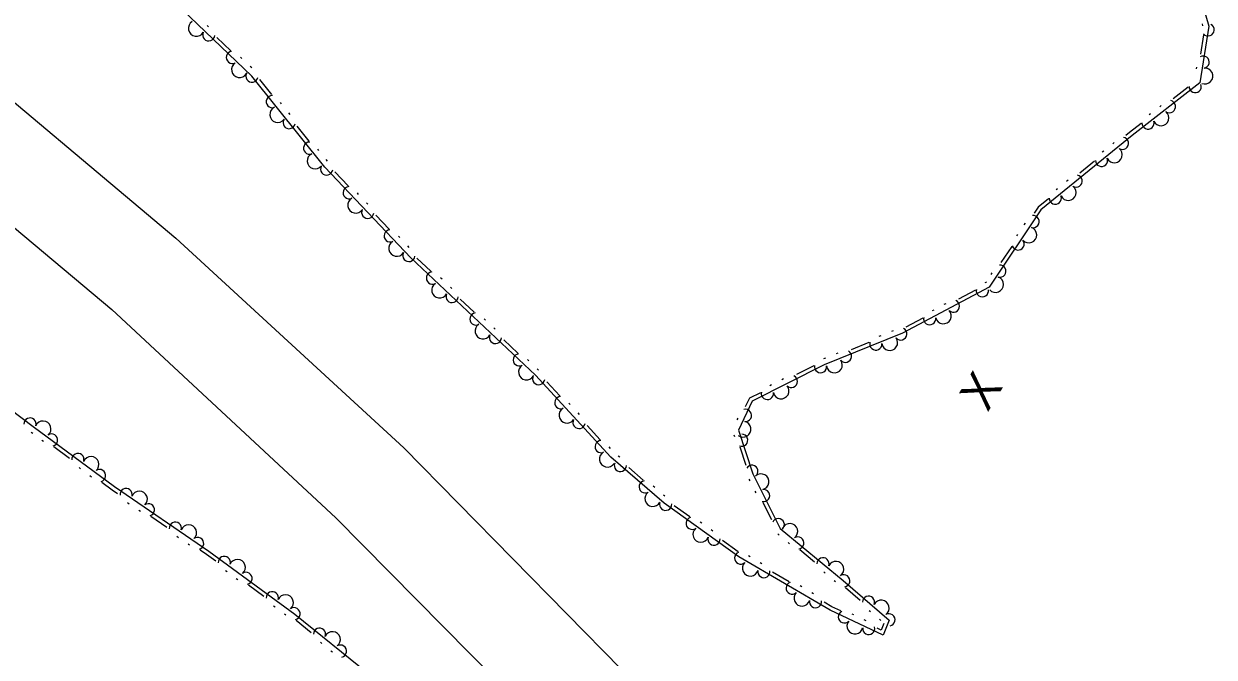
# Model space of a CAD drawing. Extents: x 2030130 to 2036320, y 723205 to 762423.
# Drawn here: x 2033698.8 to 2033952.5, y 760133.9 to 760268.9 of the extents above; entities that cross this region are included whole.
import ezdxf

# ---------------------------------------------------------------- set-up
doc = ezdxf.new("R2010")
doc.units = 0
doc.layers.add('Draft_Station Labels Major', color=7, linetype='Continuous')
doc.layers.add('Draft_Station Tics Major', color=7, linetype='Continuous')

msp = doc.modelspace()

# ---------------------------------------------------------------- linework, layer by layer
at = {"layer": 'Draft_Station Labels Major'}
for points in [[(2033680.58, 760265.74), (2033731.15, 760223.23), (2033779.8, 760178.5), (2033826.1, 760131.35), (2033869.94, 760081.9)], [(2033667.56, 760249.84), (2033717.53, 760207.99), (2033765.27, 760163.58), (2033811.07, 760117.18), (2033854.41, 760068.47)]]:
    msp.add_lwpolyline(points, dxfattribs=at)
at = {"layer": 'Draft_Station Tics Major'}
for points in [[(2033411.94, 760372.87), (2033436.62, 760363.72), (2033457.72, 760353.14), (2033472.09, 760345.15), (2033486.23, 760335.96), (2033505.08, 760321.88), (2033526.01, 760304.91), (2033549.26, 760286.66), (2033572.92, 760268.98), (2033588.53, 760260.15), (2033618.88, 760241.01), (2033641.56, 760226.3), (2033661.86, 760212.37), (2033683.46, 760196.15), (2033700.78, 760183.09), (2033718.09, 760170.27), (2033738.2, 760156.52), (2033756.52, 760143.06), (2033772.39, 760130.26)], [(2033949.39, 760275.12), (2033951.3, 760268.42), (2033949.43, 760256.31), (2033934.97, 760245.11), (2033915.56, 760229.27), (2033904.54, 760212.79), (2033886.03, 760202.95), (2033869.32, 760196.2), (2033854.03, 760188.48), (2033851.07, 760182.28), (2033854.12, 760172.95), (2033859.97, 760161.34), (2033873.42, 760150.27), (2033883.23, 760141.81), (2033881.91, 760138.58), (2033870.62, 760143.93), (2033851.14, 760155.28), (2033835.28, 760166.7), (2033823.91, 760176.51), (2033807.81, 760194.03), (2033781.27, 760219.06), (2033762.96, 760238.34), (2033747.39, 760257.77), (2033730.92, 760273.5)], [(2033738.15, 760268.29), (2033737.85, 760268.58)], [(2033949.89, 760268.88), (2033950, 760268.49)], [(2033742.91, 760263.18), (2033739.94, 760266.01)], [(2033950.18, 760266.53), (2033949.56, 760262.47)], [(2033745.27, 760261.49), (2033744.97, 760261.78)], [(2033747.34, 760259.51), (2033747.05, 760259.79)], [(2033948.71, 760259.7), (2033948.65, 760259.3)], [(2033751.61, 760253.81), (2033749.05, 760257.01)], [(2033946.96, 760255.43), (2033943.72, 760252.92)], [(2033753.73, 760251.82), (2033753.47, 760252.14)], [(2033941.19, 760251.48), (2033940.87, 760251.23)], [(2033755.52, 760249.58), (2033755.27, 760249.9)], [(2033938.92, 760249.73), (2033938.6, 760249.48)], [(2033759.56, 760243.88), (2033757, 760247.08)], [(2033936.91, 760247.65), (2033934.46, 760245.75), (2033933.66, 760245.1)], [(2033931.18, 760243.61), (2033930.86, 760243.35)], [(2033761.68, 760241.9), (2033761.42, 760242.22)], [(2033928.95, 760241.79), (2033928.63, 760241.53)], [(2033763.48, 760239.66), (2033763.22, 760239.98)], [(2033926.99, 760239.66), (2033923.81, 760237.06)], [(2033767.87, 760234.36), (2033765.04, 760237.34)], [(2033921.33, 760235.57), (2033921.01, 760235.31)], [(2033770.14, 760232.56), (2033769.86, 760232.86)], [(2033919.1, 760233.75), (2033918.79, 760233.49)], [(2033772.12, 760230.48), (2033771.83, 760230.78)], [(2033917.14, 760231.62), (2033914.95, 760229.83), (2033914.1, 760228.57)], [(2033776.62, 760225.14), (2033773.8, 760228.12)], [(2033912.17, 760226.41), (2033911.94, 760226.07)], [(2033778.9, 760223.34), (2033778.61, 760223.64)], [(2033910.57, 760224.02), (2033910.34, 760223.68)], [(2033780.87, 760221.26), (2033780.59, 760221.56)], [(2033909.32, 760221.41), (2033907.04, 760218)], [(2033785.54, 760216.16), (2033782.56, 760218.97)], [(2033905.1, 760215.84), (2033904.87, 760215.5)], [(2033787.91, 760214.49), (2033787.61, 760214.77)], [(2033790, 760212.52), (2033789.7, 760212.8)], [(2033903.94, 760213.87), (2033903.58, 760213.68)], [(2033794.79, 760207.44), (2033791.81, 760210.25)], [(2033901.6, 760212.16), (2033897.98, 760210.23)], [(2033892.71, 760207.9), (2033892.35, 760207.71)], [(2033895.25, 760209.25), (2033894.89, 760209.06)], [(2033797.16, 760205.77), (2033796.86, 760206.05)], [(2033890.37, 760206.19), (2033886.75, 760204.27)], [(2033799.25, 760203.8), (2033798.95, 760204.08)], [(2033881.41, 760202.41), (2033881.03, 760202.26)], [(2033884.07, 760203.49), (2033883.69, 760203.34)], [(2033804.04, 760198.72), (2033801.06, 760201.53)], [(2033878.9, 760200.96), (2033875.1, 760199.42)], [(2033806.41, 760197.05), (2033806.12, 760197.33)], [(2033869.62, 760197.65), (2033869.24, 760197.49)], [(2033872.28, 760198.72), (2033871.9, 760198.57)], [(2033808.5, 760195.07), (2033808.21, 760195.36)], [(2033867.12, 760196.01), (2033863.46, 760194.16)], [(2033812.99, 760189.61), (2033810.22, 760192.63)], [(2033860.71, 760193.23), (2033860.34, 760193.05)], [(2033855.77, 760190.28), (2033853.41, 760189.09), (2033852.54, 760187.27)], [(2033858.15, 760191.94), (2033857.78, 760191.75)], [(2033815.23, 760187.77), (2033814.96, 760188.08)], [(2033817.18, 760185.66), (2033816.9, 760185.96)], [(2033850.93, 760184.85), (2033850.76, 760184.48)], [(2033821.59, 760180.25), (2033818.81, 760183.27)], [(2033700.34, 760181.88), (2033700.67, 760181.63)], [(2033702.65, 760180.17), (2033702.98, 760179.93)], [(2033850.09, 760181.32), (2033850.21, 760180.93)], [(2033705.2, 760178.79), (2033708.5, 760176.35)], [(2033823.83, 760178.41), (2033823.55, 760178.71)], [(2033851.37, 760178.72), (2033852.65, 760174.82)], [(2033825.78, 760176.51), (2033825.47, 760176.78)], [(2033710.56, 760174.31), (2033710.89, 760174.07)], [(2033712.87, 760172.6), (2033713.2, 760172.36)], [(2033830.8, 760171.65), (2033827.69, 760174.33)], [(2033715.42, 760171.22), (2033717.61, 760169.6), (2033718.77, 760168.81)], [(2033833.24, 760170.08), (2033832.92, 760170.35)], [(2033853.31, 760171.83), (2033853.49, 760171.47)], [(2033720.91, 760166.85), (2033721.25, 760166.62)], [(2033835.41, 760168.2), (2033835.1, 760168.47)], [(2033854.6, 760169.27), (2033854.78, 760168.9)], [(2033856.26, 760166.89), (2033858.1, 760163.23)], [(2033723.28, 760165.23), (2033723.62, 760165)], [(2033840.7, 760163.81), (2033837.37, 760166.2)], [(2033725.88, 760163.95), (2033729.27, 760161.63)], [(2033843.27, 760162.46), (2033842.93, 760162.7)], [(2033731.4, 760159.68), (2033731.74, 760159.45)], [(2033845.6, 760160.79), (2033845.26, 760161.03)], [(2033859.46, 760160.17), (2033859.77, 760159.91)], [(2033733.77, 760158.06), (2033734.11, 760157.82)], [(2033736.38, 760156.77), (2033737.72, 760155.85), (2033739.69, 760154.41)], [(2033851.01, 760156.38), (2033847.69, 760158.78)], [(2033861.67, 760158.35), (2033861.99, 760158.09)], [(2033864.15, 760156.84), (2033867.31, 760154.23)], [(2033853.6, 760155.27), (2033853.24, 760155.48)], [(2033741.76, 760152.38), (2033742.09, 760152.14)], [(2033856.08, 760153.83), (2033855.72, 760154.03)], [(2033861.89, 760149.96), (2033858.35, 760152.03)], [(2033869.27, 760152.09), (2033869.59, 760151.83)], [(2033744.07, 760150.68), (2033744.41, 760150.44)], [(2033746.63, 760149.31), (2033749.94, 760146.88)], [(2033864.58, 760148.87), (2033864.23, 760149.08)], [(2033871.49, 760150.27), (2033871.8, 760150.01)], [(2033867.06, 760147.43), (2033866.71, 760147.63)], [(2033873.93, 760148.75), (2033877.04, 760146.07)], [(2033752.01, 760144.85), (2033752.34, 760144.61)], [(2033872.9, 760143.75), (2033871, 760144.66), (2033869.33, 760145.63)], [(2033754.32, 760143.15), (2033754.65, 760142.91)], [(2033756.82, 760141.77), (2033760.01, 760139.19)], [(2033875.67, 760142.9), (2033875.3, 760143.07)], [(2033878.27, 760141.67), (2033877.89, 760141.84)], [(2033878.94, 760143.88), (2033879.25, 760143.62)], [(2033881.12, 760142.01), (2033881.43, 760141.74)], [(2033882.04, 760141.07), (2033881.48, 760139.69), (2033880.68, 760140.07)], [(2033761.99, 760137.07), (2033762.31, 760136.82)], [(2033764.22, 760135.27), (2033764.54, 760135.01)]]:
    msp.add_lwpolyline(points, dxfattribs=at)
for centre, radius, start, end in [((2033735.55, 760267.94), 1.69, 122.2783, 330.3508), ((2033951.18, 760267.62), 1.3, 221.999, 62.7956), ((2033738.19, 760266.55), 1.3, 154.7495, 355.546), ((2033743.23, 760261.74), 1.3, 97.083, 297.8796), ((2033950.12, 760260.73), 1.3, 279.6655, 120.462), ((2033744.74, 760259.16), 1.69, 122.2783, 330.3508), ((2033747.38, 760257.77), 1.3, 147.1407, 347.9373), ((2033950.49, 760257.77), 1.69, 247.1943, 95.2668), ((2033948.43, 760255.53), 1.3, 178.506, 19.3026), ((2033751.74, 760252.33), 1.3, 89.4743, 290.2708), ((2033752.9, 760249.58), 1.69, 114.6695, 322.742), ((2033942.92, 760251.26), 1.3, 236.1725, 76.9691), ((2033755.33, 760247.85), 1.3, 147.1407, 347.9373), ((2033938.38, 760247.75), 1.3, 178.506, 19.3026), ((2033941.15, 760248.86), 1.69, 203.7013, 51.7738), ((2033759.69, 760242.41), 1.3, 89.4743, 290.2708), ((2033932.91, 760243.43), 1.3, 237.6573, 78.4539), ((2033760.85, 760239.66), 1.69, 114.6695, 322.742), ((2033931.2, 760240.98), 1.69, 205.1861, 53.2586), ((2033763.32, 760237.96), 1.3, 151.9563, 352.7529), ((2033928.46, 760239.8), 1.3, 179.9908, 20.7874), ((2033923.06, 760235.39), 1.3, 237.6573, 78.4539), ((2033768.12, 760232.9), 1.3, 94.2899, 295.0864), ((2033921.36, 760232.94), 1.69, 205.1861, 53.2586), ((2033769.5, 760230.26), 1.69, 119.4852, 327.5576), ((2033918.61, 760231.76), 1.3, 179.9908, 20.7874), ((2033772.07, 760228.74), 1.3, 151.9563, 352.7529), ((2033913.87, 760226.75), 1.3, 254.6548, 95.4514), ((2033912.96, 760223.91), 1.69, 222.1836, 70.2561), ((2033776.87, 760223.69), 1.3, 94.2899, 295.0864), ((2033910.68, 760221.98), 1.3, 196.9883, 37.7849), ((2033778.26, 760221.04), 1.69, 119.4852, 327.5576), ((2033780.83, 760219.52), 1.3, 151.9563, 352.7529), ((2033785.87, 760214.72), 1.3, 97.4594, 298.2559), ((2033906.81, 760216.18), 1.3, 254.6548, 95.4514), ((2033787.4, 760212.15), 1.69, 122.6547, 330.7271), ((2033905.89, 760213.34), 1.69, 222.1836, 70.2561), ((2033790.05, 760210.78), 1.3, 155.1258, 355.9224), ((2033896.91, 760208.74), 1.3, 226.4208, 67.2174), ((2033903.07, 760212.01), 1.3, 168.7543, 9.5509), ((2033894.76, 760206.67), 1.69, 193.9496, 42.0221), ((2033795.13, 760205.99), 1.3, 97.4594, 298.2559), ((2033796.65, 760203.43), 1.69, 122.6547, 330.7271), ((2033891.84, 760206.05), 1.3, 168.7543, 9.5509), ((2033799.3, 760202.06), 1.3, 155.1258, 355.9224), ((2033885.67, 760202.81), 1.3, 220.4519, 61.2485), ((2033880.35, 760200.66), 1.3, 162.7854, 3.582), ((2033883.32, 760200.97), 1.69, 187.9807, 36.0532), ((2033804.38, 760197.27), 1.3, 97.4594, 298.2559), ((2033873.88, 760198.04), 1.3, 220.4519, 61.2485), ((2033805.9, 760194.71), 1.69, 122.6547, 330.7271), ((2033868.59, 760195.83), 1.3, 167.5482, 8.3448), ((2033871.53, 760196.21), 1.69, 187.9807, 36.0532), ((2033808.5, 760193.28), 1.3, 150.9932, 351.7898), ((2033862.36, 760192.69), 1.3, 225.2147, 66.0112), ((2033857.24, 760190.1), 1.3, 167.5482, 8.3448), ((2033860.17, 760190.66), 1.69, 192.7435, 40.816), ((2033813.22, 760188.15), 1.3, 93.3267, 294.1233), ((2033700.09, 760183.6), 1.3, 341.4151, 182.2117), ((2033814.55, 760185.48), 1.69, 118.522, 326.5945), ((2033817.1, 760183.92), 1.3, 150.9932, 351.7898), ((2033852.57, 760185.44), 1.3, 262.9404, 103.737), ((2033702.88, 760182.55), 1.69, 309.4433, 157.5158), ((2033852.08, 760182.49), 1.69, 230.4692, 78.5417), ((2033704.7, 760180.18), 1.3, 284.2481, 125.0446), ((2033821.82, 760178.78), 1.3, 93.3267, 294.1233), ((2033851.77, 760180.15), 1.3, 248.8885, 89.6851), ((2033710.3, 760176.03), 1.3, 341.9145, 182.7111), ((2033823.15, 760176.12), 1.69, 118.522, 326.5945), ((2033713.1, 760174.98), 1.69, 309.4433, 157.5158), ((2033825.91, 760174.78), 1.3, 157.6415, 358.4381), ((2033853.94, 760173.52), 1.3, 306.555, 147.3516), ((2033714.92, 760172.62), 1.3, 284.2481, 125.0446), ((2033855.88, 760171.29), 1.69, 282.7115, 130.784), ((2033720.59, 760168.56), 1.3, 344.0818, 184.8784), ((2033723.42, 760167.62), 1.69, 311.6107, 159.6831), ((2033831.19, 760170.22), 1.3, 99.975, 300.7716), ((2033856.44, 760168.36), 1.3, 257.5162, 98.3128), ((2033832.83, 760167.72), 1.69, 125.1703, 333.2428), ((2033835.56, 760166.49), 1.3, 162.6893, 3.4859), ((2033725.33, 760165.32), 1.3, 286.4154, 127.2119), ((2033731.08, 760161.39), 1.3, 344.0818, 184.8784), ((2033733.92, 760160.44), 1.69, 311.6107, 159.6831), ((2033841.22, 760162.42), 1.3, 105.0229, 305.8194), ((2033859.57, 760162.13), 1.3, 315.1827, 155.9792), ((2033862.03, 760160.71), 1.69, 306.4967, 154.5692), ((2033735.82, 760158.15), 1.3, 286.4154, 127.2119), ((2033843.07, 760160.08), 1.69, 130.2181, 338.2906), ((2033845.87, 760159.07), 1.3, 162.6893, 3.4859), ((2033863.72, 760158.25), 1.3, 281.3014, 122.098), ((2033741.5, 760154.1), 1.3, 342.1334, 182.93), ((2033744.3, 760153.06), 1.69, 309.6623, 157.7347), ((2033851.56, 760155.03), 1.3, 110.5395, 311.3361), ((2033869.1, 760153.82), 1.3, 338.9679, 179.7645), ((2033871.84, 760152.63), 1.69, 306.4967, 154.5692), ((2033746.13, 760150.7), 1.3, 284.467, 125.2635), ((2033853.63, 760152.88), 1.69, 135.7348, 343.8073), ((2033856.52, 760152.14), 1.3, 168.206, 9.0025), ((2033862.54, 760148.63), 1.3, 110.5395, 311.3361), ((2033873.53, 760150.17), 1.3, 280.0102, 120.8068), ((2033751.74, 760146.57), 1.3, 342.1334, 182.93), ((2033754.54, 760145.53), 1.69, 309.6623, 157.7347), ((2033864.61, 760146.48), 1.69, 135.7348, 343.8073), ((2033878.81, 760145.62), 1.3, 337.6767, 178.4732), ((2033756.37, 760143.17), 1.3, 284.467, 125.2635), ((2033867.5, 760145.74), 1.3, 168.206, 9.0025), ((2033881.52, 760144.37), 1.69, 305.2055, 153.2779), ((2033873.66, 760142.49), 1.3, 115.4177, 316.2142), ((2033875.9, 760140.52), 1.69, 140.6129, 348.6854), ((2033883.16, 760141.87), 1.3, 280.0102, 120.8068), ((2033761.8, 760138.8), 1.3, 339.5469, 180.3435), ((2033764.55, 760137.64), 1.69, 307.0757, 155.1482), ((2033878.85, 760140.03), 1.3, 173.0841, 13.8807), ((2033766.27, 760135.2), 1.3, 281.8805, 122.677)]:
    msp.add_arc(centre, radius, start, end, dxfattribs=at)

# ---------------------------------------------------------------- texts
msp.add_text('X', height=7.38, rotation=58.9267, dxfattribs=at).set_placement((2033904.18, 760185.99))

doc.saveas('drawing.dxf')
